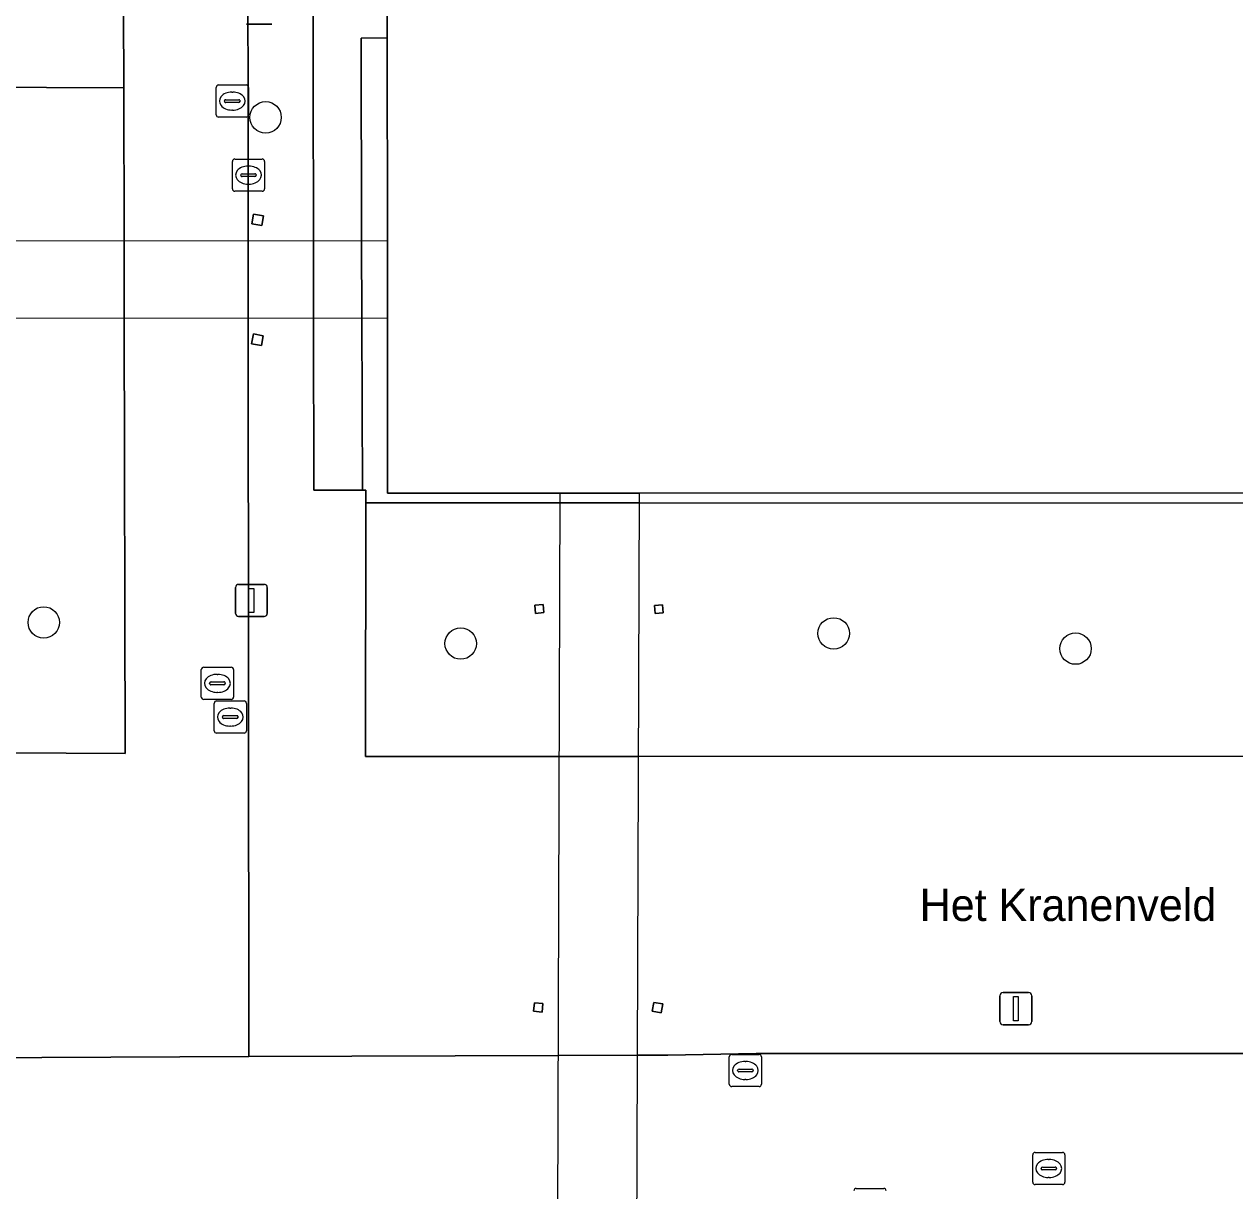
# Model space of a CAD drawing. Extents: x 161477 to 163040, y 383680 to 384871.
# Drawn here: x 161860.15 to 161897.77, y 384114.93 to 384151.17 of the extents above; entities that cross this region are included whole.
import ezdxf

# ---------------------------------------------------------------- set-up
doc = ezdxf.new("R2010")
doc.units = 0
for name, color, linetype in [('IMGEO_Boom', 7, 'Continuous'), ('IMGEO_Dek', 7, 'Continuous'), ('IMGEO_Groenvoorziening', 7, 'Continuous'), ('IMGEO_Kolk', 7, 'Continuous'), ('IMGEO_Lichtmast', 7, 'Continuous'), ('IMGEO_Openbare_ruimte_label', 7, 'Continuous'), ('IMGEO_Pand', 7, 'Continuous'), ('IMGEO_Pijler', 7, 'Continuous'), ('IMGEO_Rijbaan_lokaal_open', 7, 'Continuous'), ('IMGEO_Rioolput', 7, 'Continuous'), ('IMGEO_Terreindeel_onvherhard', 7, 'Continuous'), ('IMGEO_Voetpad_gesloten', 7, 'Continuous'), ('IMGEO_Voetpad_halfverhard', 7, 'Continuous'), ('IMGEO_Voetpad_open', 7, 'Continuous')]:
    doc.layers.add(name, color=color, linetype=linetype)

msp = doc.modelspace()

# ---------------------------------------------------------------- linework, layer by layer
at = {"layer": 'IMGEO_Boom'}
for centre in [(161867.654, 384148.278), (161860.763, 384132.587), (161885.306, 384132.246), (161873.719, 384131.933), (161892.822, 384131.776)]:
    msp.add_circle(centre, 0.489, dxfattribs=at)
at = {"layer": 'IMGEO_Dek'}
for points in [[(161818.801, 384142.079), (161871.441, 384142.039), (161871.439, 384144.431), (161818.802, 384144.456)], [(161879.273, 384136.604), (161876.803, 384136.603), (161876.693, 384104.521), (161879.156, 384104.495)]]:
    msp.add_lwpolyline(points, close=True, dxfattribs=at)
at = {"layer": 'IMGEO_Groenvoorziening'}
msp.add_lwpolyline([(161844.945, 384128.623), (161863.289, 384128.521), (161863.262, 384142.045), (161863.257, 384144.435), (161863.247, 384149.196), (161856.031, 384149.227)], dxfattribs=at)
for points in [[(161920.067, 384133.782), (161919.897, 384133.781), (161919.889, 384136.28), (161916.787, 384136.298), (161879.272, 384136.301), (161876.802, 384136.301), (161870.773, 384136.302), (161870.762, 384128.419), (161876.775, 384128.422), (161879.243, 384128.424), (161916.936, 384128.444), (161924.395, 384128.462), (161924.432, 384132.187), (161920.015, 384132.225)], [(161876.047, 384132.871), (161876.024, 384133.124), (161876.277, 384133.147), (161876.3, 384132.894)], [(161879.76, 384132.868), (161879.743, 384133.116), (161879.991, 384133.133), (161880.008, 384132.885)]]:
    msp.add_lwpolyline(points, close=True, dxfattribs=at)
at = {"layer": 'IMGEO_Kolk'}
for p, q in [((161866.12, 384148.359), (161866.12, 384149.211)), ((161866.195, 384149.285), (161867.047, 384149.285)), ((161867.121, 384149.211), (161867.121, 384148.359)), ((161866.422, 384148.828), (161866.82, 384148.828)), ((161866.608, 384149.065), (161866.633, 384149.065)), ((161866.379, 384148.779), (161866.379, 384148.791)), ((161866.817, 384148.742), (161866.419, 384148.742)), ((161866.631, 384148.505), (161866.606, 384148.505)), ((161866.863, 384148.791), (161866.863, 384148.779)), ((161867.047, 384148.285), (161866.195, 384148.285)), ((161866.699, 384146.985), (161867.551, 384146.985)), ((161866.624, 384146.059), (161866.624, 384146.911)), ((161867.112, 384146.765), (161867.137, 384146.765)), ((161867.625, 384146.911), (161867.625, 384146.059)), ((161866.883, 384146.479), (161866.883, 384146.491)), ((161867.321, 384146.442), (161866.923, 384146.442)), ((161866.926, 384146.528), (161867.324, 384146.528)), ((161867.135, 384146.205), (161867.11, 384146.205)), ((161867.367, 384146.491), (161867.367, 384146.479)), ((161867.551, 384145.985), (161866.699, 384145.985)), ((161865.733, 384131.196), (161866.585, 384131.196)), ((161865.658, 384130.27), (161865.658, 384131.122)), ((161866.146, 384130.976), (161866.171, 384130.976)), ((161866.659, 384131.122), (161866.659, 384130.27)), ((161865.917, 384130.69), (161865.917, 384130.702)), ((161866.355, 384130.653), (161865.957, 384130.653)), ((161865.96, 384130.739), (161866.358, 384130.739)), ((161866.169, 384130.416), (161866.144, 384130.416)), ((161866.401, 384130.702), (161866.401, 384130.69)), ((161866.585, 384130.196), (161865.733, 384130.196)), ((161866.059, 384129.223), (161866.059, 384130.075)), ((161866.134, 384130.149), (161866.986, 384130.149)), ((161867.06, 384130.075), (161867.06, 384129.223)), ((161866.318, 384129.643), (161866.318, 384129.655)), ((161866.361, 384129.692), (161866.759, 384129.692)), ((161866.547, 384129.929), (161866.572, 384129.929)), ((161866.802, 384129.655), (161866.802, 384129.643)), ((161866.756, 384129.606), (161866.358, 384129.606)), ((161866.57, 384129.369), (161866.545, 384129.369)), ((161866.986, 384129.149), (161866.134, 384129.149)), ((161882.139, 384119.17), (161882.991, 384119.17)), ((161882.064, 384118.244), (161882.064, 384119.096)), ((161882.552, 384118.95), (161882.577, 384118.95)), ((161883.065, 384119.096), (161883.065, 384118.244)), ((161882.323, 384118.664), (161882.323, 384118.676)), ((161882.761, 384118.627), (161882.363, 384118.627)), ((161882.366, 384118.713), (161882.764, 384118.713)), ((161882.575, 384118.39), (161882.55, 384118.39)), ((161882.807, 384118.676), (161882.807, 384118.664)), ((161882.991, 384118.17), (161882.139, 384118.17))]:
    msp.add_line(p, q, dxfattribs=at)
for points in [[(161866.12, 384148.359), (161866.12, 384149.211)], [(161866.195, 384149.285), (161867.047, 384149.285)], [(161867.121, 384149.211), (161867.121, 384148.359)], [(161867.047, 384148.285), (161866.195, 384148.285)], [(161866.699, 384146.985), (161867.551, 384146.985)], [(161866.624, 384146.059), (161866.624, 384146.911)], [(161867.625, 384146.911), (161867.625, 384146.059)], [(161867.551, 384145.985), (161866.699, 384145.985)], [(161865.733, 384131.196), (161866.585, 384131.196)], [(161865.658, 384130.27), (161865.658, 384131.122)], [(161866.659, 384131.122), (161866.659, 384130.27)], [(161866.585, 384130.196), (161865.733, 384130.196)], [(161866.059, 384129.223), (161866.059, 384130.075)], [(161866.134, 384130.149), (161866.986, 384130.149)], [(161867.06, 384130.075), (161867.06, 384129.223)], [(161866.986, 384129.149), (161866.134, 384129.149)], [(161882.139, 384119.17), (161882.991, 384119.17)], [(161882.064, 384118.244), (161882.064, 384119.096)], [(161883.065, 384119.096), (161883.065, 384118.244)], [(161882.991, 384118.17), (161882.139, 384118.17)]]:
    msp.add_lwpolyline(points, dxfattribs=at)
for centre, radius, start, end in [((161866.197, 384149.209), 0.0765, 91.552, 178.448), ((161866.197, 384149.209), 0.0765, 91.552, 178.448), ((161867.045, 384149.209), 0.0765, 1.552, 88.448), ((161867.045, 384149.209), 0.0765, 1.552, 88.448), ((161866.419, 384148.788), 0.0403, 85.8775, 175.7526), ((161866.824, 384148.79), 0.0386, 1.7309, 96.639), ((161866.416, 384148.778), 0.0366, 178.938, 274.7102), ((161866.82, 384148.785), 0.043, 264.8664, 352.4533), ((161866.197, 384148.361), 0.0765, 181.552, 268.448), ((161866.197, 384148.361), 0.0765, 181.552, 268.448), ((161867.045, 384148.361), 0.0765, 271.552, 358.448), ((161867.045, 384148.361), 0.0765, 271.552, 358.448), ((161866.701, 384146.909), 0.0765, 91.552, 178.448), ((161866.701, 384146.909), 0.0765, 91.552, 178.448), ((161867.549, 384146.909), 0.0765, 1.552, 88.448), ((161867.549, 384146.909), 0.0765, 1.552, 88.448), ((161866.923, 384146.488), 0.0403, 85.8775, 175.7526), ((161866.92, 384146.478), 0.0366, 178.938, 274.7102), ((161867.324, 384146.485), 0.043, 264.8664, 352.4533), ((161867.328, 384146.49), 0.0386, 1.7309, 96.639), ((161866.701, 384146.061), 0.0765, 181.552, 268.448), ((161866.701, 384146.061), 0.0765, 181.552, 268.448), ((161867.549, 384146.061), 0.0765, 271.552, 358.448), ((161867.549, 384146.061), 0.0765, 271.552, 358.448), ((161865.735, 384131.12), 0.0765, 91.552, 178.448), ((161865.735, 384131.12), 0.0765, 91.552, 178.448), ((161866.583, 384131.12), 0.0765, 1.552, 88.448), ((161866.583, 384131.12), 0.0765, 1.552, 88.448), ((161865.957, 384130.699), 0.0403, 85.8775, 175.7526), ((161865.954, 384130.689), 0.0366, 178.938, 274.7102), ((161866.358, 384130.696), 0.043, 264.8664, 352.4533), ((161866.362, 384130.701), 0.0386, 1.7309, 96.639), ((161865.735, 384130.272), 0.0765, 181.552, 268.448), ((161865.735, 384130.272), 0.0765, 181.552, 268.448), ((161866.136, 384130.073), 0.0765, 91.552, 178.448), ((161866.136, 384130.073), 0.0765, 91.552, 178.448), ((161866.583, 384130.272), 0.0765, 271.552, 358.448), ((161866.583, 384130.272), 0.0765, 271.552, 358.448), ((161866.984, 384130.073), 0.0765, 1.552, 88.448), ((161866.984, 384130.073), 0.0765, 1.552, 88.448), ((161866.358, 384129.652), 0.0403, 85.8775, 175.7526), ((161866.355, 384129.642), 0.0366, 178.938, 274.7102), ((161866.759, 384129.649), 0.043, 264.8664, 352.4533), ((161866.763, 384129.654), 0.0386, 1.7309, 96.639), ((161866.136, 384129.225), 0.0765, 181.552, 268.448), ((161866.136, 384129.225), 0.0765, 181.552, 268.448), ((161866.984, 384129.225), 0.0765, 271.552, 358.448), ((161866.984, 384129.225), 0.0765, 271.552, 358.448), ((161882.141, 384119.094), 0.0765, 91.552, 178.448), ((161882.141, 384119.094), 0.0765, 91.552, 178.448), ((161882.989, 384119.094), 0.0765, 1.552, 88.448), ((161882.989, 384119.094), 0.0765, 1.552, 88.448), ((161882.363, 384118.673), 0.0403, 85.8775, 175.7526), ((161882.36, 384118.663), 0.0366, 178.938, 274.7102), ((161882.764, 384118.67), 0.043, 264.8664, 352.4533), ((161882.768, 384118.675), 0.0386, 1.7309, 96.639), ((161882.141, 384118.246), 0.0765, 181.552, 268.448), ((161882.141, 384118.246), 0.0765, 181.552, 268.448), ((161882.989, 384118.246), 0.0765, 271.552, 358.448), ((161882.989, 384118.246), 0.0765, 271.552, 358.448)]:
    msp.add_arc(centre, radius, start, end, dxfattribs=at)
for centre, major_axis, ratio, start_param, end_param in [((161866.607, 384148.785), (-0.387, 0.002), 0.722429, 4.712389, 7.853982), ((161866.632, 384148.785), (-0.39, 0.002), 0.717154, 1.570796, 4.712389), ((161867.111, 384146.485), (-0.387, 0.002), 0.722429, 4.712389, 7.853982), ((161867.136, 384146.485), (-0.39, 0.002), 0.717154, 1.570796, 4.712389), ((161866.145, 384130.696), (-0.387, 0.002), 0.722429, 4.712389, 7.853982), ((161866.17, 384130.696), (-0.39, 0.002), 0.717154, 1.570796, 4.712389), ((161866.546, 384129.649), (-0.387, 0.002), 0.722429, 4.712389, 7.853982), ((161866.571, 384129.649), (-0.39, 0.002), 0.717154, 1.570796, 4.712389), ((161882.551, 384118.67), (-0.387, 0.002), 0.722429, 4.712389, 7.853982), ((161882.576, 384118.67), (-0.39, 0.002), 0.717154, 1.570796, 4.712389)]:
    msp.add_ellipse(centre, major_axis=major_axis, ratio=ratio, start_param=start_param, end_param=end_param, dxfattribs=at)
at = {"layer": 'IMGEO_Lichtmast'}
for p, q in [((161867.852, 384151.172), (161867.062, 384151.172)), ((161867.062, 384151.172), (161867.852, 384151.172)), ((161866.718, 384132.871), (161866.718, 384133.671)), ((161866.718, 384133.671), (161866.718, 384132.871)), ((161866.818, 384133.771), (161867.608, 384133.771)), ((161867.608, 384133.771), (161866.818, 384133.771)), ((161867.708, 384133.671), (161867.708, 384132.871)), ((161867.708, 384132.871), (161867.708, 384133.671)), ((161867.608, 384132.771), (161866.818, 384132.771)), ((161866.818, 384132.771), (161867.608, 384132.771)), ((161890.474, 384120.188), (161890.474, 384120.988)), ((161890.474, 384120.988), (161890.474, 384120.188)), ((161890.574, 384121.088), (161891.364, 384121.088)), ((161891.364, 384121.088), (161890.574, 384121.088)), ((161891.464, 384120.988), (161891.464, 384120.188)), ((161891.464, 384120.188), (161891.464, 384120.988)), ((161891.364, 384120.088), (161890.574, 384120.088)), ((161890.574, 384120.088), (161891.364, 384120.088))]:
    msp.add_line(p, q, dxfattribs=at)
for points in [[(161867.138, 384133.646), (161867.288, 384133.646), (161867.288, 384132.896), (161867.138, 384132.896), (161867.138, 384133.646)], [(161890.894, 384120.963), (161891.044, 384120.963), (161891.044, 384120.213), (161890.894, 384120.213), (161890.894, 384120.963)]]:
    msp.add_lwpolyline(points, dxfattribs=at)
for centre, start, end in [((161866.818, 384133.671), 90, 180), ((161866.818, 384133.671), 90, 180), ((161867.608, 384133.671), 0, 90), ((161867.608, 384133.671), 360, 90), ((161866.818, 384132.871), 180, 270), ((161866.818, 384132.871), 180, 270), ((161867.608, 384132.871), 270, 0), ((161867.608, 384132.871), 270, 0), ((161890.574, 384120.988), 90, 180), ((161890.574, 384120.988), 90, 180), ((161891.364, 384120.988), 0, 90), ((161891.364, 384120.988), 360, 90), ((161890.574, 384120.188), 180, 270), ((161890.574, 384120.188), 180, 270), ((161891.364, 384120.188), 270, 0), ((161891.364, 384120.188), 270, 0)]:
    msp.add_arc(centre, 0.1, start, end, dxfattribs=at)
at = {"layer": 'IMGEO_Pand'}
msp.add_lwpolyline([(161945.027, 384175.873), (161926.299, 384175.874), (161925.232, 384175.874), (161914.028, 384175.874), (161911.525, 384175.874), (161886.732, 384175.875), (161885.455, 384175.875), (161871.412, 384175.876), (161871.419, 384168.026), (161871.419, 384167.933), (161871.423, 384163.067), (161871.423, 384162.958), (161871.432, 384153.064), (161871.434, 384150.746), (161871.439, 384144.431), (161871.441, 384142.039), (161871.446, 384136.601), (161876.803, 384136.603), (161879.273, 384136.604), (161919.889, 384136.62), (161935.366, 384136.609)], dxfattribs=at)
at = {"layer": 'IMGEO_Pijler'}
for points in [[(161867.28, 384145.274), (161867.229, 384144.968), (161867.535, 384144.917), (161867.586, 384145.223)], [(161867.28, 384141.551), (161867.222, 384141.247), (161867.526, 384141.189), (161867.584, 384141.493)], [(161876.047, 384132.871), (161876.3, 384132.894), (161876.277, 384133.147), (161876.024, 384133.124)], [(161879.76, 384132.868), (161880.008, 384132.885), (161879.991, 384133.133), (161879.743, 384133.116)], [(161876.247, 384120.482), (161876.274, 384120.747), (161876.009, 384120.774), (161875.982, 384120.509)], [(161879.945, 384120.461), (161879.995, 384120.736), (161879.72, 384120.786), (161879.67, 384120.511)]]:
    msp.add_lwpolyline(points, close=True, dxfattribs=at)
at = {"layer": 'IMGEO_Rijbaan_lokaal_open'}
msp.add_lwpolyline([(161949.647, 384119.202), (161949.401, 384119.206), (161949.26, 384119.206), (161931.139, 384119.201), (161931.035, 384119.201), (161930.575, 384119.21), (161924.611, 384119.191), (161907.804, 384119.203), (161907.646, 384119.202), (161904.742, 384119.192), (161882.894, 384119.196), (161880.154, 384119.146), (161880.064, 384119.146), (161879.209, 384119.143), (161876.743, 384119.134), (161867.138, 384119.099), (161858.546, 384119.067)], dxfattribs=at)
at = {"layer": 'IMGEO_Rioolput'}
for p, q in [((161891.566, 384116.126), (161892.418, 384116.126)), ((161891.491, 384115.2), (161891.491, 384116.052)), ((161891.979, 384115.906), (161892.004, 384115.906)), ((161892.492, 384116.052), (161892.492, 384115.2)), ((161891.75, 384115.62), (161891.75, 384115.632)), ((161892.188, 384115.583), (161891.79, 384115.583)), ((161891.793, 384115.669), (161892.191, 384115.669)), ((161892.002, 384115.346), (161891.977, 384115.346)), ((161892.234, 384115.632), (161892.234, 384115.62)), ((161886.009, 384115.006), (161886.861, 384115.006)), ((161892.418, 384115.126), (161891.566, 384115.126))]:
    msp.add_line(p, q, dxfattribs=at)
for points in [[(161891.566, 384116.126), (161892.418, 384116.126)], [(161891.491, 384115.2), (161891.491, 384116.052)], [(161892.492, 384116.052), (161892.492, 384115.2)], [(161886.009, 384115.006), (161886.861, 384115.006)], [(161892.418, 384115.126), (161891.566, 384115.126)]]:
    msp.add_lwpolyline(points, dxfattribs=at)
for centre, radius, start, end in [((161891.568, 384116.05), 0.0765, 91.552, 178.448), ((161891.568, 384116.05), 0.0765, 91.552, 178.448), ((161892.416, 384116.05), 0.0765, 1.552, 88.448), ((161892.416, 384116.05), 0.0765, 1.552, 88.448), ((161891.79, 384115.629), 0.0403, 85.8775, 175.7526), ((161891.787, 384115.619), 0.0366, 178.938, 274.7102), ((161892.191, 384115.626), 0.043, 264.8664, 352.4533), ((161892.195, 384115.631), 0.0386, 1.7309, 96.639), ((161886.011, 384114.93), 0.0765, 91.552, 178.448), ((161886.011, 384114.93), 0.0765, 91.552, 178.448), ((161886.859, 384114.93), 0.0765, 1.552, 88.448), ((161886.859, 384114.93), 0.0765, 1.552, 88.448), ((161891.568, 384115.202), 0.0765, 181.552, 268.448), ((161891.568, 384115.202), 0.0765, 181.552, 268.448), ((161892.416, 384115.202), 0.0765, 271.552, 358.448), ((161892.416, 384115.202), 0.0765, 271.552, 358.448)]:
    msp.add_arc(centre, radius, start, end, dxfattribs=at)
for centre, major_axis, ratio, start_param, end_param in [((161891.978, 384115.626), (-0.387, 0.002), 0.722429, 4.712389, 7.853982), ((161892.003, 384115.626), (-0.39, 0.002), 0.717154, 1.570796, 4.712389)]:
    msp.add_ellipse(centre, major_axis=major_axis, ratio=ratio, start_param=start_param, end_param=end_param, dxfattribs=at)
at = {"layer": 'IMGEO_Terreindeel_onvherhard'}
msp.add_lwpolyline([(161871.439, 384144.431), (161871.434, 384150.746), (161870.622, 384150.744), (161870.64, 384144.431), (161870.647, 384142.04), (161870.663, 384136.694), (161870.765, 384136.696), (161870.773, 384136.302), (161876.802, 384136.301), (161879.272, 384136.301), (161916.787, 384136.298), (161919.889, 384136.28), (161919.889, 384136.62), (161879.273, 384136.604), (161876.803, 384136.603), (161871.446, 384136.601), (161871.441, 384142.039)], close=True, dxfattribs=at)
at = {"layer": 'IMGEO_Voetpad_gesloten'}
for points in [[(161871.439, 384144.431), (161818.802, 384144.456), (161818.801, 384142.079), (161871.441, 384142.039)], [(161876.803, 384136.603), (161876.693, 384104.521), (161879.156, 384104.495), (161879.273, 384136.604)]]:
    msp.add_lwpolyline(points, close=True, dxfattribs=at)
at = {"layer": 'IMGEO_Voetpad_halfverhard'}
msp.add_lwpolyline([(161863.239, 384151.611), (161856.034, 384151.593), (161855.992, 384155.169), (161846.414, 384155.222), (161846.399, 384145.662), (161855.978, 384145.626), (161856.031, 384149.227), (161863.247, 384149.196)], close=True, dxfattribs=at)
at = {"layer": 'IMGEO_Voetpad_open'}
for points in [[(161852.453, 384187.71), (161860.783, 384187.71), (161863.207, 384187.71), (161863.207, 384186.237), (161863.207, 384185.898), (161863.239, 384151.611), (161863.247, 384149.196), (161863.257, 384144.435), (161863.262, 384142.045), (161863.289, 384128.521), (161844.945, 384128.623)], [(161858.546, 384119.067), (161867.138, 384119.099), (161867.115, 384142.042), (161867.113, 384144.433), (161867.101, 384156.554), (161867.101, 384156.591), (161867.081, 384176.171), (161867.078, 384179.395), (161867.055, 384180.764), (161867.055, 384180.903), (161867.053, 384181.699), (161867.046, 384184.991), (161867.041, 384187.711), (161871.621, 384187.719), (161886.491, 384187.746), (161890.029, 384187.752), (161911.288, 384187.79), (161911.343, 384187.79), (161914.35, 384187.795), (161942.475, 384187.845)], [(161867.101, 384156.554), (161867.113, 384144.433), (161867.115, 384142.042), (161867.138, 384119.099), (161876.743, 384119.134), (161879.209, 384119.143), (161880.064, 384119.146), (161880.154, 384119.146), (161882.894, 384119.196), (161904.742, 384119.192), (161907.646, 384119.202), (161907.804, 384119.203), (161924.611, 384119.191)], [(161925.664, 384132.213), (161924.432, 384132.187), (161924.395, 384128.462), (161916.936, 384128.444), (161879.243, 384128.424), (161876.775, 384128.422), (161870.762, 384128.419), (161870.773, 384136.302), (161870.765, 384136.696), (161870.663, 384136.694), (161869.156, 384136.694), (161869.146, 384142.041), (161869.141, 384144.432), (161869.122, 384154.637)]]:
    msp.add_lwpolyline(points, dxfattribs=at)
for points in [[(161870.622, 384150.744), (161871.434, 384150.746), (161871.432, 384153.064), (161870.614, 384153.062), (161870.611, 384154.478), (161870.61, 384154.629), (161869.122, 384154.637), (161869.141, 384144.432), (161869.146, 384142.041), (161869.156, 384136.694), (161870.663, 384136.694), (161870.647, 384142.04), (161870.64, 384144.431)], [(161867.535, 384144.917), (161867.229, 384144.968), (161867.28, 384145.274), (161867.586, 384145.223)], [(161867.526, 384141.189), (161867.222, 384141.247), (161867.28, 384141.551), (161867.584, 384141.493)], [(161876.247, 384120.482), (161875.982, 384120.509), (161876.009, 384120.774), (161876.274, 384120.747)], [(161879.945, 384120.461), (161879.67, 384120.511), (161879.72, 384120.786), (161879.995, 384120.736)]]:
    msp.add_lwpolyline(points, close=True, dxfattribs=at)

# ---------------------------------------------------------------- texts
at = {"layer": 'IMGEO_Openbare_ruimte_label'}
msp.add_text('Het Kranenveld', height=1, dxfattribs=at).set_placement((161887.978, 384123.313))

doc.saveas('drawing.dxf')
